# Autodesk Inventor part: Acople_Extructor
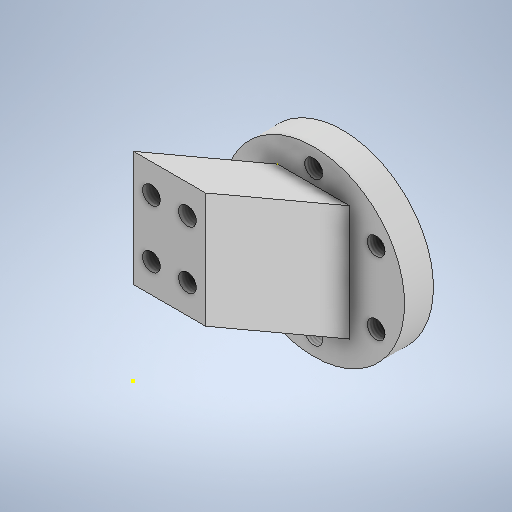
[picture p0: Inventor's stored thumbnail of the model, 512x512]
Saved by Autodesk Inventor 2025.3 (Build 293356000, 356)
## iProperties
Created: 2025-11
Part Number: Acople_Extructor
Material: Acero
Document SubType Name: Modeling
Designer: Dell
Density: 7.85 g/cm^3
Appearance: Placa
Mass: 617.106 g
Surface Area: 163.899 cm^2
Volume: 78.6123 cm^3
Author: Dell
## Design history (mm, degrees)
sketch "Boceto1"
  geometry: C1 r 31.5 at (0, 0); C2 r 3.1 at (0, 25); C3 r 3.1 at (-21.651, 12.5); C4 r 3.1 at (-21.651, -12.5); C5 r 3.1 at (0, -25); C6 r 3.1 at (21.651, -12.5); C7 r 3.1 at (21.651, 12.5); 1 further point
  constraints: 7 centre point, 1 coincident, 13 other
  dimensions: "d5" = 360 deg dimension on point (0, 0) C2.centre (derived)
extrude "Extrusión1" new body sketch "Boceto1" distance "d7" = 10; taper "d8" = 0 deg
sketch "Boceto2"
  geometry: L1 (-12.5, 20)-(12.5, 20); L2 (-12.5, -20)-(12.5, -20); L3 (12.5, 20)-(12.5, -20); L4 (-12.5, 20)-(-12.5, -20); 1 further point
  constraints: 8 end point, 2 horizontal, 1 perpendicular, 1 vertical
extrude "Extrusión2" join sketch "Boceto2" distance "d12" = 50; taper "d13" = 0 deg
sketch "Boceto3"
  geometry: L1 (0, 40)-(0, 0) reference; 2 further points
sketch "Boceto4"
  geometry: L1 (0, 40)-(0, 0) reference; L2 (50, 0)-(50, 40) reference; L3 (0, 40)-(23.094, 40); L4 (0, 0)-(50, 28.868); L5 (0, 0)-(57.735, 0); L6 (50, 28.868)-(50, 0); L7 (0, 40)-(50, 40); L8 (50, 28.453)-(50, 40); L9 (0, 40)-(50, 40); L10 (50, 28.453)-(50, 40); L11 (50, 28.868)-(50, 0); L12 (0, 0)-(50, 0); L13 (0, 40)-(50, 68.868); L14 (0, 40)-(57.735, 40); L15 (50, 68.868)-(50, 40); 1 further point
  constraints: 26 end point, 7 collinear, 3 horizontal, 2 equal length, 2 point on line, 1 vertical
  dimensions: "d16" = 30 deg angle of L5 L4; "d17" = 30 deg angle of L14 L13
extrude "Extrusión5" join sketch "Boceto4" distance "d22" = 25; taper "d23" = 0 deg
extrude "Extrusión6" cut sketch "Boceto4" distance "d24" = 25; taper "d25" = 0 deg
sketch "Boceto6"
  geometry: L1 (-12.5, 48.868)-(12.5, 48.868) reference; L2 (12.5, 48.868)-(6.25, 48.868); L3 (-12.5, 8.868)-(12.5, 8.868) reference; C1 r 3.1 at (6.25, 38.868); C2 r 3.1 at (-6.25, 38.868); C3 r 3.1 at (6.25, 18.868); C4 r 3.1 at (-6.25, 18.868); 1 further point
  constraints: 4 centre point, 2 end point, 1 point on line
  dimensions: "d29" = 6.2 diameter of C1; "d31" = 6.2 diameter of C2; "d33" = 6.2 diameter of C3; "d34" = 6.2 diameter of C4
extrude "Extrusión7" cut sketch "Boceto6" distance "d35" = 6.2 (= d29); taper "d36" = 0 deg
feature "Rosca1" dims "d37" = 80, "d38" = 0
feature "Rosca2" dims "d39" = 80, "d40" = 0
feature "Rosca3" dims "d41" = 80, "d42" = 0
feature "Rosca4" dims "d43" = 80, "d44" = 0
feature "Rosca5" dims "d45" = 80, "d46" = 0
feature "Rosca6" dims "d47" = 80, "d48" = 0
feature "Rosca7" dims "d49" = 80, "d50" = 0
feature "Rosca8" dims "d51" = 80, "d52" = 0
feature "Rosca9" dims "d53" = 80, "d54" = 0
feature "Rosca10" dims "d55" = 80, "d56" = 0
node "Sólido1"
node "Boceto - Patrón circular1" dims "d5" = 360 deg (derived)
